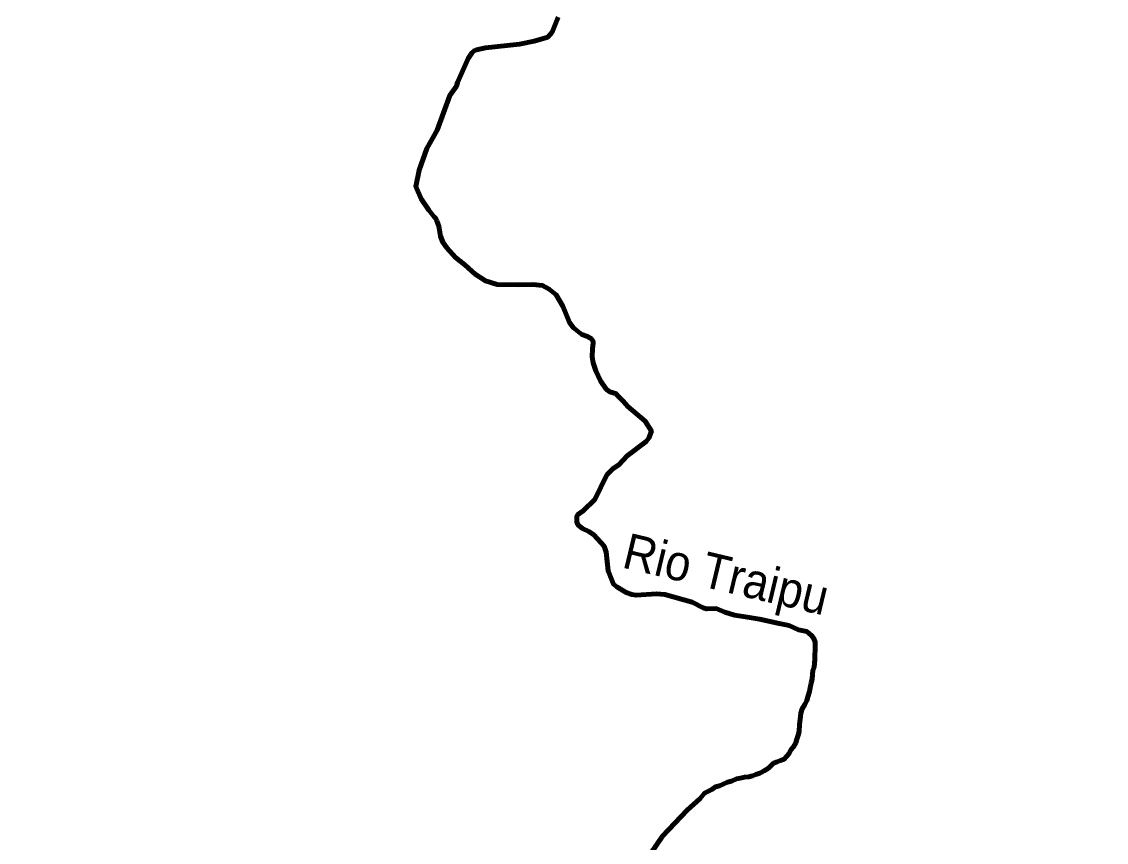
# Model space of a CAD drawing. Extents: x -1643653 to 4543381, y 1624270 to 13878484.
# Drawn here: x 709746 to 724990, y 8906261 to 8917800 of the extents above; entities that cross this region are included whole.
import ezdxf
from ezdxf.enums import TextEntityAlignment as Align

# ---------------------------------------------------------------- set-up
doc = ezdxf.new("R2010")
doc.units = 0
doc.header["$LTSCALE"] = 200
for name, color, linetype, lineweight in [('1', 7, 'Continuous', 13), ('24', 7, 'Continuous', 25), ('53', 7, 'Continuous', 106)]:
    doc.layers.add(name, color=color, linetype=linetype, lineweight=lineweight)
doc.layers.add('49', color=7, linetype='Continuous')

msp = doc.modelspace()

# ---------------------------------------------------------------- linework, layer by layer
at = {"layer": '1', "lineweight": 25}
msp.add_spline([(814781, 9009175.5), (814787.2, 9009173.4), (814796.9, 9009173.4), (814799.4, 9009172.4), (814805.1, 9009174.5), (814805.6, 9009176.5), (814811.7, 9009179.5), (814811.7, 9009179.5), (814801.5, 9009181), (814790.7, 9009181.5), (814784.1, 9009183.1), (814777.4, 9009185.1), (814778.4, 9009175.5)], degree=3, dxfattribs=at)
at = {"layer": '24', "lineweight": 53}
for points in [[(717287.5, 8917863.5), (717202.1, 8917652.5), (717139.9, 8917584.2), (716949.9, 8917526.3), (716744.6, 8917482.9), (716262.7, 8917433.2), (716138.9, 8917405.7), (716105.4, 8917390.9), (716076.8, 8917365.2), (716021.3, 8917281.8), (715870.4, 8916945.9), (715855.1, 8916891.8), (715765.5, 8916761), (715585.2, 8916273.3), (715439.9, 8916014.5), (715332.6, 8915712.1), (715285.6, 8915483), (715360.4, 8915309.1), (715466.5, 8915151.7), (715544.8, 8915057.8), (715568.8, 8915033.9), (715582.8, 8914999.5)], [(715582.8, 8914999.5), (715607.3, 8914926.5), (715630.8, 8914782.1), (715664.2, 8914698.4), (715720.4, 8914621.3), (715841.4, 8914484.8), (715976.3, 8914382.9), (716121.9, 8914251.7), (716262.7, 8914158.2), (716430.6, 8914102.4), (716723.3, 8914098.2), (716931, 8914106.3), (717067.3, 8914089.8), (717160, 8914040), (717258.6, 8913960.8), (717350.2, 8913798.9), (717444.9, 8913569.6), (717500.7, 8913495.3), (717620.4, 8913403.7), (717696.9, 8913374.6), (717753.4, 8913338.3), (717771.3, 8913315.3), (717779.7, 8913284.7), (717767.4, 8913198.7), (717765.2, 8913088.6), (717776, 8913003.3), (717816.4, 8912891.5), (717881.6, 8912752), (717959.7, 8912633.8), (718012.2, 8912595.1), (718103.9, 8912566), (718108.4, 8912552.9), (718200.6, 8912462.7), (718263.8, 8912388), (718510.9, 8912180.7), (718595.9, 8912042.5), (718559.6, 8911942), (718525.1, 8911895.3), (718256.7, 8911695.7), (718139.8, 8911569.1), (718058.8, 8911518.2), (717971, 8911425.9), (717799.8, 8911079.5), (717637.2, 8910919.9), (717559.9, 8910863.9), (717548.7, 8910844.9), (717546.6, 8910765.8), (717564.2, 8910723.9), (717629.5, 8910673.2), (717717.9, 8910632.5), (717786.1, 8910583.9), (717932.5, 8910426.1), (717961.9, 8910338.5), (717987.1, 8910076.6), (718063.3, 8909892.7), (718110.2, 8909851.7), (718240.9, 8909774.5), (718323.8, 8909744.9), (718380.9, 8909735.3), (718665.9, 8909753.1), (718783.6, 8909747.4), (719169.5, 8909639.4), (719326.4, 8909556.3)], [(719326.4, 8909556.3), (719371.3, 8909542.5), (719371.3, 8909542.5), (719504.5, 8909548.1), (719504.5, 8909548.1), (719504.5, 8909548.1), (719626.5, 8909498.2)], [(719626.5, 8909498.2), (719765.2, 8909453.8), (719765.2, 8909453.8), (719765.2, 8909453.8), (719765.2, 8909453.8), (719948.4, 8909426.1), (719948.4, 8909426.1), (719948.4, 8909426.1), (720114.8, 8909398.4), (720114.8, 8909398.4), (720114.8, 8909398.4), (720392.3, 8909337.4), (720392.3, 8909337.4), (720392.3, 8909337.4), (720392.3, 8909337.4), (720531, 8909309.6), (720531, 8909309.6), (720531, 8909309.6), (720664.2, 8909248.6), (720780.7, 8909226.5), (720848.9, 8909167.8), (720879.1, 8909126.9), (720899.1, 8909075.8), (720898.7, 8909024.9), (720898.3, 8908963.8), (720892.8, 8908897.6), (720892.3, 8908831.3), (720886.9, 8908780.4), (720886.5, 8908724.4), (720865.8, 8908678.7), (720860.4, 8908622.7), (720854.9, 8908561.6), (720844.3, 8908500.6), (720828.6, 8908434.4), (720818, 8908383.6), (720797.2, 8908307.3), (720781.6, 8908256.4), (720750.7, 8908200.6), (720714.6, 8908139.7), (720699, 8908078.7), (720693.5, 8908027.8), (720680.1, 8907917.9)], [(720680.1, 8907917.9), (720671.8, 8907819.1), (720661.2, 8907768.2), (720640.5, 8907712.3), (720624.9, 8907661.5), (720594, 8907605.6), (720558.1, 8907560), (720532.3, 8907509.3), (720496.4, 8907468.7), (720460.5, 8907428.2), (720409.6, 8907413.3), (720363.7, 8907393.2), (720312.7, 8907373.1), (720276.8, 8907337.7), (720241, 8907302.3), (720179.7, 8907267), (720118.4, 8907231.8), (720062.3, 8907216.8), (720016.4, 8907196.8), (719965.5, 8907181.8), (719909.5, 8907177.1), (719843.3, 8907162.2), (719792.3, 8907152.3), (719720.9, 8907122.2), (719664.9, 8907107.3), (719603.6, 8907077.1), (719552.6, 8907057.1), (719496.6, 8907042.2), (719445.4, 8907001.8), (719343.4, 8906951.5), (719283.6, 8906877)], [(719283.6, 8906877), (719100.8, 8906711), (718751.9, 8906345.6), (718502.7, 8905980.3), (718452.8, 8905797.7), (718403, 8905681.4), (718353.1, 8905299.5), (718286.7, 8905067), (718187, 8904867.8), (718137.2, 8904701.7), (718054.1, 8904552.2), (717859.9, 8904374.3), (717854.7, 8904369.6)]]:
    msp.add_lwpolyline(points, dxfattribs=at)
at = {"layer": '53'}
for points in [[(717287.5, 8917863.5), (717202.1, 8917652.5), (717139.9, 8917584.2), (716949.9, 8917526.3), (716744.6, 8917482.9), (716262.7, 8917433.2), (716138.9, 8917405.7), (716105.4, 8917390.9), (716076.8, 8917365.2), (716021.3, 8917281.8), (715870.4, 8916945.9), (715855.1, 8916891.8), (715765.5, 8916761), (715585.2, 8916273.3), (715439.9, 8916014.5), (715332.6, 8915712.1), (715285.6, 8915483), (715360.4, 8915309.1), (715466.5, 8915151.7), (715544.8, 8915057.8), (715568.8, 8915033.9), (715582.8, 8914999.5)], [(717287.5, 8917863.5), (717202.1, 8917652.5), (717139.9, 8917584.2), (716949.9, 8917526.3), (716744.6, 8917482.9), (716262.7, 8917433.2), (716138.9, 8917405.7), (716105.4, 8917390.9), (716076.8, 8917365.2), (716021.3, 8917281.8), (715870.4, 8916945.9), (715855.1, 8916891.8), (715765.5, 8916761), (715585.2, 8916273.3), (715439.9, 8916014.5), (715332.6, 8915712.1), (715285.6, 8915483), (715360.4, 8915309.1), (715466.5, 8915151.7), (715544.8, 8915057.8), (715568.8, 8915033.9), (715582.8, 8914999.5)], [(717287.5, 8917863.5), (717202.1, 8917652.5), (717139.9, 8917584.2), (716949.9, 8917526.3), (716744.6, 8917482.9), (716262.7, 8917433.2), (716138.9, 8917405.7), (716105.4, 8917390.9), (716076.8, 8917365.2), (716021.3, 8917281.8), (715870.4, 8916945.9), (715855.1, 8916891.8), (715765.5, 8916761), (715585.2, 8916273.3), (715439.9, 8916014.5), (715332.6, 8915712.1), (715285.6, 8915483), (715360.4, 8915309.1), (715466.5, 8915151.7), (715544.8, 8915057.8), (715568.8, 8915033.9), (715582.8, 8914999.5)], [(715582.8, 8914999.5), (715607.3, 8914926.5), (715630.8, 8914782.1), (715664.2, 8914698.4), (715720.4, 8914621.3), (715841.4, 8914484.8), (715976.3, 8914382.9), (716121.9, 8914251.7), (716262.7, 8914158.2), (716430.6, 8914102.4), (716723.3, 8914098.2), (716931, 8914106.3), (717067.3, 8914089.8), (717160, 8914040), (717258.6, 8913960.8), (717350.2, 8913798.9), (717444.9, 8913569.6), (717500.7, 8913495.3), (717620.4, 8913403.7), (717696.9, 8913374.6), (717753.4, 8913338.3), (717771.3, 8913315.3), (717779.7, 8913284.7), (717767.4, 8913198.7), (717765.2, 8913088.6), (717776, 8913003.3), (717816.4, 8912891.5), (717881.6, 8912752), (717959.7, 8912633.8), (718012.2, 8912595.1), (718103.9, 8912566), (718108.4, 8912552.9), (718200.6, 8912462.7), (718263.8, 8912388), (718510.9, 8912180.7), (718595.9, 8912042.5), (718559.6, 8911942), (718525.1, 8911895.3), (718256.7, 8911695.7), (718139.8, 8911569.1), (718058.8, 8911518.2), (717971, 8911425.9), (717799.8, 8911079.5), (717637.2, 8910919.9), (717559.9, 8910863.9), (717548.7, 8910844.9), (717546.6, 8910765.8), (717564.2, 8910723.9), (717629.5, 8910673.2), (717717.9, 8910632.5), (717786.1, 8910583.9), (717932.5, 8910426.1), (717961.9, 8910338.5), (717987.1, 8910076.6), (718063.3, 8909892.7), (718110.2, 8909851.7), (718240.9, 8909774.5), (718323.8, 8909744.9), (718380.9, 8909735.3), (718665.9, 8909753.1), (718783.6, 8909747.4), (719169.5, 8909639.4), (719326.4, 8909556.3)], [(715582.8, 8914999.5), (715607.3, 8914926.5), (715630.8, 8914782.1), (715664.2, 8914698.4), (715720.4, 8914621.3), (715841.4, 8914484.8), (715976.3, 8914382.9), (716121.9, 8914251.7), (716262.7, 8914158.2), (716430.6, 8914102.4), (716723.3, 8914098.2), (716931, 8914106.3), (717067.3, 8914089.8), (717160, 8914040), (717258.6, 8913960.8), (717350.2, 8913798.9), (717444.9, 8913569.6), (717500.7, 8913495.3), (717620.4, 8913403.7), (717696.9, 8913374.6), (717753.4, 8913338.3), (717771.3, 8913315.3), (717779.7, 8913284.7), (717767.4, 8913198.7), (717765.2, 8913088.6), (717776, 8913003.3), (717816.4, 8912891.5), (717881.6, 8912752), (717959.7, 8912633.8), (718012.2, 8912595.1), (718103.9, 8912566), (718108.4, 8912552.9), (718200.6, 8912462.7), (718263.8, 8912388), (718510.9, 8912180.7), (718595.9, 8912042.5), (718559.6, 8911942), (718525.1, 8911895.3), (718256.7, 8911695.7), (718139.8, 8911569.1), (718058.8, 8911518.2), (717971, 8911425.9), (717799.8, 8911079.5), (717637.2, 8910919.9), (717559.9, 8910863.9), (717548.7, 8910844.9), (717546.6, 8910765.8), (717564.2, 8910723.9), (717629.5, 8910673.2), (717717.9, 8910632.5), (717786.1, 8910583.9), (717932.5, 8910426.1), (717961.9, 8910338.5), (717987.1, 8910076.6), (718063.3, 8909892.7), (718110.2, 8909851.7), (718240.9, 8909774.5), (718323.8, 8909744.9), (718380.9, 8909735.3), (718665.9, 8909753.1), (718783.6, 8909747.4), (719169.5, 8909639.4), (719326.4, 8909556.3)], [(715582.8, 8914999.5), (715607.3, 8914926.5), (715630.8, 8914782.1), (715664.2, 8914698.4), (715720.4, 8914621.3), (715841.4, 8914484.8), (715976.3, 8914382.9), (716121.9, 8914251.7), (716262.7, 8914158.2), (716430.6, 8914102.4), (716723.3, 8914098.2), (716931, 8914106.3), (717067.3, 8914089.8), (717160, 8914040), (717258.6, 8913960.8), (717350.2, 8913798.9), (717444.9, 8913569.6), (717500.7, 8913495.3), (717620.4, 8913403.7), (717696.9, 8913374.6), (717753.4, 8913338.3), (717771.3, 8913315.3), (717779.7, 8913284.7), (717767.4, 8913198.7), (717765.2, 8913088.6), (717776, 8913003.3), (717816.4, 8912891.5), (717881.6, 8912752), (717959.7, 8912633.8), (718012.2, 8912595.1), (718103.9, 8912566), (718108.4, 8912552.9), (718200.6, 8912462.7), (718263.8, 8912388), (718510.9, 8912180.7), (718595.9, 8912042.5), (718559.6, 8911942), (718525.1, 8911895.3), (718256.7, 8911695.7), (718139.8, 8911569.1), (718058.8, 8911518.2), (717971, 8911425.9), (717799.8, 8911079.5), (717637.2, 8910919.9), (717559.9, 8910863.9), (717548.7, 8910844.9), (717546.6, 8910765.8), (717564.2, 8910723.9), (717629.5, 8910673.2), (717717.9, 8910632.5), (717786.1, 8910583.9), (717932.5, 8910426.1), (717961.9, 8910338.5), (717987.1, 8910076.6), (718063.3, 8909892.7), (718110.2, 8909851.7), (718240.9, 8909774.5), (718323.8, 8909744.9), (718380.9, 8909735.3), (718665.9, 8909753.1), (718783.6, 8909747.4), (719169.5, 8909639.4), (719326.4, 8909556.3)], [(719326.4, 8909556.3), (719371.3, 8909542.5), (719371.3, 8909542.5), (719504.5, 8909548.1), (719504.5, 8909548.1), (719504.5, 8909548.1), (719626.5, 8909498.2)], [(719326.4, 8909556.3), (719371.3, 8909542.5), (719371.3, 8909542.5), (719504.5, 8909548.1), (719504.5, 8909548.1), (719504.5, 8909548.1), (719626.5, 8909498.2)], [(719326.4, 8909556.3), (719371.3, 8909542.5), (719371.3, 8909542.5), (719504.5, 8909548.1), (719504.5, 8909548.1), (719504.5, 8909548.1), (719626.5, 8909498.2)], [(719626.5, 8909498.2), (719765.2, 8909453.8), (719765.2, 8909453.8), (719765.2, 8909453.8), (719765.2, 8909453.8), (719948.4, 8909426.1), (719948.4, 8909426.1), (719948.4, 8909426.1), (720114.8, 8909398.4), (720114.8, 8909398.4), (720114.8, 8909398.4), (720392.3, 8909337.4), (720392.3, 8909337.4), (720392.3, 8909337.4), (720392.3, 8909337.4), (720531, 8909309.6), (720531, 8909309.6), (720531, 8909309.6), (720664.2, 8909248.6), (720780.7, 8909226.5), (720848.9, 8909167.8), (720879.1, 8909126.9), (720899.1, 8909075.8), (720898.7, 8909024.9), (720898.3, 8908963.8), (720892.8, 8908897.6), (720892.3, 8908831.3), (720886.9, 8908780.4), (720886.5, 8908724.4), (720865.8, 8908678.7), (720860.4, 8908622.7), (720854.9, 8908561.6), (720844.3, 8908500.6), (720828.6, 8908434.4), (720818, 8908383.6), (720797.2, 8908307.3), (720781.6, 8908256.4), (720750.7, 8908200.6), (720714.6, 8908139.7), (720699, 8908078.7), (720693.5, 8908027.8), (720680.1, 8907917.9)], [(719626.5, 8909498.2), (719765.2, 8909453.8), (719765.2, 8909453.8), (719765.2, 8909453.8), (719765.2, 8909453.8), (719948.4, 8909426.1), (719948.4, 8909426.1), (719948.4, 8909426.1), (720114.8, 8909398.4), (720114.8, 8909398.4), (720114.8, 8909398.4), (720392.3, 8909337.4), (720392.3, 8909337.4), (720392.3, 8909337.4), (720392.3, 8909337.4), (720531, 8909309.6), (720531, 8909309.6), (720531, 8909309.6), (720664.2, 8909248.6), (720780.7, 8909226.5), (720848.9, 8909167.8), (720879.1, 8909126.9), (720899.1, 8909075.8), (720898.7, 8909024.9), (720898.3, 8908963.8), (720892.8, 8908897.6), (720892.3, 8908831.3), (720886.9, 8908780.4), (720886.5, 8908724.4), (720865.8, 8908678.7), (720860.4, 8908622.7), (720854.9, 8908561.6), (720844.3, 8908500.6), (720828.6, 8908434.4), (720818, 8908383.6), (720797.2, 8908307.3), (720781.6, 8908256.4), (720750.7, 8908200.6), (720714.6, 8908139.7), (720699, 8908078.7), (720693.5, 8908027.8), (720680.1, 8907917.9)], [(719626.5, 8909498.2), (719765.2, 8909453.8), (719765.2, 8909453.8), (719765.2, 8909453.8), (719765.2, 8909453.8), (719948.4, 8909426.1), (719948.4, 8909426.1), (719948.4, 8909426.1), (720114.8, 8909398.4), (720114.8, 8909398.4), (720114.8, 8909398.4), (720392.3, 8909337.4), (720392.3, 8909337.4), (720392.3, 8909337.4), (720392.3, 8909337.4), (720531, 8909309.6), (720531, 8909309.6), (720531, 8909309.6), (720664.2, 8909248.6), (720780.7, 8909226.5), (720848.9, 8909167.8), (720879.1, 8909126.9), (720899.1, 8909075.8), (720898.7, 8909024.9), (720898.3, 8908963.8), (720892.8, 8908897.6), (720892.3, 8908831.3), (720886.9, 8908780.4), (720886.5, 8908724.4), (720865.8, 8908678.7), (720860.4, 8908622.7), (720854.9, 8908561.6), (720844.3, 8908500.6), (720828.6, 8908434.4), (720818, 8908383.6), (720797.2, 8908307.3), (720781.6, 8908256.4), (720750.7, 8908200.6), (720714.6, 8908139.7), (720699, 8908078.7), (720693.5, 8908027.8), (720680.1, 8907917.9)], [(720680.1, 8907917.9), (720671.8, 8907819.1), (720661.2, 8907768.2), (720640.5, 8907712.3), (720624.9, 8907661.5), (720594, 8907605.6), (720558.1, 8907560), (720532.3, 8907509.3), (720496.4, 8907468.7), (720460.5, 8907428.2), (720409.6, 8907413.3), (720363.7, 8907393.2), (720312.7, 8907373.1), (720276.8, 8907337.7), (720241, 8907302.3), (720179.7, 8907267), (720118.4, 8907231.8), (720062.3, 8907216.8), (720016.4, 8907196.8), (719965.5, 8907181.8), (719909.5, 8907177.1), (719843.3, 8907162.2), (719792.3, 8907152.3), (719720.9, 8907122.2), (719664.9, 8907107.3), (719603.6, 8907077.1), (719552.6, 8907057.1), (719496.6, 8907042.2), (719445.4, 8907001.8), (719343.4, 8906951.5), (719283.6, 8906877)], [(720680.1, 8907917.9), (720671.8, 8907819.1), (720661.2, 8907768.2), (720640.5, 8907712.3), (720624.9, 8907661.5), (720594, 8907605.6), (720558.1, 8907560), (720532.3, 8907509.3), (720496.4, 8907468.7), (720460.5, 8907428.2), (720409.6, 8907413.3), (720363.7, 8907393.2), (720312.7, 8907373.1), (720276.8, 8907337.7), (720241, 8907302.3), (720179.7, 8907267), (720118.4, 8907231.8), (720062.3, 8907216.8), (720016.4, 8907196.8), (719965.5, 8907181.8), (719909.5, 8907177.1), (719843.3, 8907162.2), (719792.3, 8907152.3), (719720.9, 8907122.2), (719664.9, 8907107.3), (719603.6, 8907077.1), (719552.6, 8907057.1), (719496.6, 8907042.2), (719445.4, 8907001.8), (719343.4, 8906951.5), (719283.6, 8906877)], [(720680.1, 8907917.9), (720671.8, 8907819.1), (720661.2, 8907768.2), (720640.5, 8907712.3), (720624.9, 8907661.5), (720594, 8907605.6), (720558.1, 8907560), (720532.3, 8907509.3), (720496.4, 8907468.7), (720460.5, 8907428.2), (720409.6, 8907413.3), (720363.7, 8907393.2), (720312.7, 8907373.1), (720276.8, 8907337.7), (720241, 8907302.3), (720179.7, 8907267), (720118.4, 8907231.8), (720062.3, 8907216.8), (720016.4, 8907196.8), (719965.5, 8907181.8), (719909.5, 8907177.1), (719843.3, 8907162.2), (719792.3, 8907152.3), (719720.9, 8907122.2), (719664.9, 8907107.3), (719603.6, 8907077.1), (719552.6, 8907057.1), (719496.6, 8907042.2), (719445.4, 8907001.8), (719343.4, 8906951.5), (719283.6, 8906877)], [(719283.6, 8906877), (719100.8, 8906711), (718751.9, 8906345.6), (718502.7, 8905980.3), (718452.8, 8905797.7), (718403, 8905681.4), (718353.1, 8905299.5), (718286.7, 8905067), (718187, 8904867.8), (718137.2, 8904701.7), (718054.1, 8904552.2), (717859.9, 8904374.3), (717854.7, 8904369.6)], [(719283.6, 8906877), (719100.8, 8906711), (718751.9, 8906345.6), (718502.7, 8905980.3), (718452.8, 8905797.7), (718403, 8905681.4), (718353.1, 8905299.5), (718286.7, 8905067), (718187, 8904867.8), (718137.2, 8904701.7), (718054.1, 8904552.2), (717859.9, 8904374.3), (717854.7, 8904369.6)], [(719283.6, 8906877), (719100.8, 8906711), (718751.9, 8906345.6), (718502.7, 8905980.3), (718452.8, 8905797.7), (718403, 8905681.4), (718353.1, 8905299.5), (718286.7, 8905067), (718187, 8904867.8), (718137.2, 8904701.7), (718054.1, 8904552.2), (717859.9, 8904374.3), (717854.7, 8904369.6)]]:
    msp.add_lwpolyline(points, dxfattribs=at)

# ---------------------------------------------------------------- texts
at = {"layer": '49', "width": 0.95}
msp.add_text('Rio Traipu', height=500, rotation=346.601, dxfattribs=at).set_placement((719591, 8909789.6), align=Align.CENTER)

doc.saveas('drawing.dxf')
